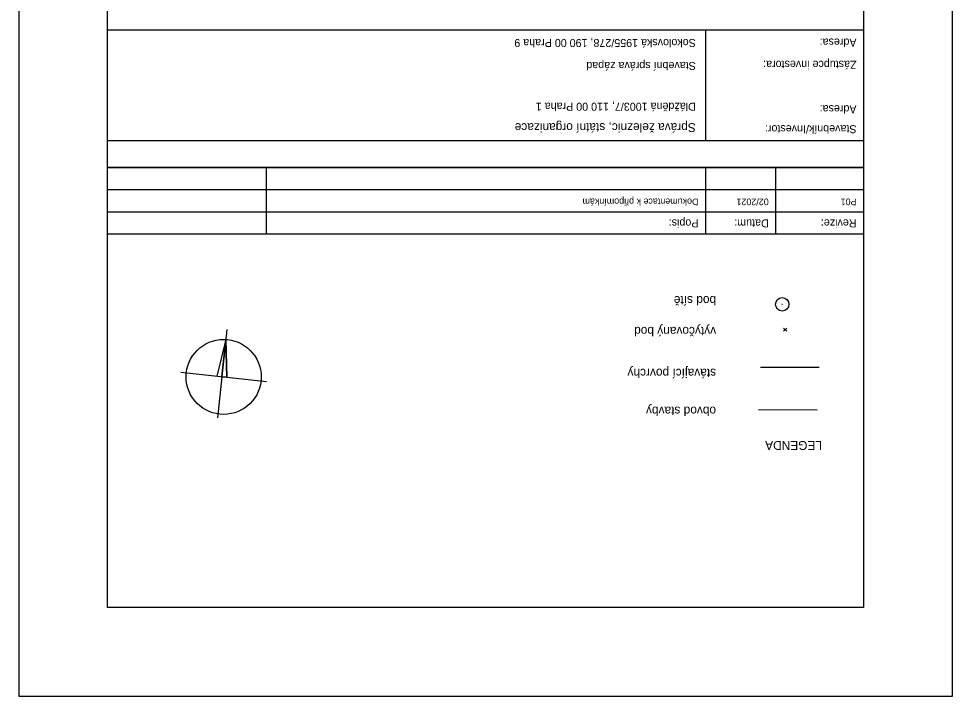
# Model space of a CAD drawing. Extents: x -728476.8 to -728424.3, y -1073086.9 to -1073012.7.
# Drawn here: x -728476.8 to -728424.3, y -1073086.9 to -1073048.8 of the extents above; entities that cross this region are included whole.
import ezdxf

# ---------------------------------------------------------------- set-up
doc = ezdxf.new("R2010")
doc.units = 0
for name, color, linetype in [('_NOR-šraf_+-0', 7, 'Continuous'), ('_NOR-šraf_+12', 7, 'Continuous'), ('A1_OBVOD Spravy železnic', 7, 'Continuous'), ('B3_body_popiska', 7, 'Continuous'), ('Default', 7, 'Continuous'), ('KOS_nové prvky VO', 7, 'Continuous'), ('KTA_členění PS a SO', 7, 'Continuous'), ('ZA_02_Dočasný_do_1_roku', 7, 'Continuous'), ('ZZZ_popisky', 7, 'Continuous')]:
    doc.layers.add(name, color=color, linetype=linetype)

# ---------------------------------------------------------------- blocks, each defined once
blk = doc.blocks.new('C692')
at = {"layer": 'ZA_02_Dočasný_do_1_roku'}
for p, q in [((-0.018, 0.018), (0.018, -0.018)), ((-0.018, -0.018), (0.018, 0.018))]:
    blk.add_line(p, q, dxfattribs=at)
blk = doc.blocks.new('C015')
at = {"layer": 'B3_body_popiska'}
blk.add_line((-0.005, 0), (0.005, 0), dxfattribs=at)
blk.add_circle((0, 0), 0.0756, dxfattribs=at)

msp = doc.modelspace()

# ---------------------------------------------------------------- linework, layer by layer
at = {"layer": '_NOR-šraf_+-0'}
msp.add_line((-728438.176, -1073049.404), (-728438.176, -1073055.654), dxfattribs=at)
msp.add_lwpolyline([(-728429.288, -1073055.654), (-728471.788, -1073055.654), (-728471.788, -1073049.404), (-728429.288, -1073049.404)], close=True, dxfattribs=at)
at = {"layer": '_NOR-šraf_+12'}
for p, q in [((-728431.771, -1073068.408), (-728435.078, -1073068.405)), ((-728431.883, -1073070.797), (-728435.19, -1073070.793))]:
    msp.add_line(p, q, dxfattribs=at)
at = {"layer": 'Default'}
msp.add_lwpolyline([(-728424.288, -1073012.654), (-728476.788, -1073012.654), (-728476.788, -1073086.904), (-728424.288, -1073086.904)], close=True, dxfattribs=at)
msp.add_lwpolyline([(-728424.288, -1073012.654), (-728476.788, -1073012.654), (-728476.788, -1073086.904), (-728424.288, -1073086.904)], close=True, dxfattribs=at)
at = {"layer": 'KOS_nové prvky VO'}
for p, q in [((-728429.288, -1073057.159), (-728471.788, -1073057.159)), ((-728462.863, -1073057.159), (-728462.863, -1073060.909)), ((-728438.176, -1073057.159), (-728438.176, -1073060.909)), ((-728434.226, -1073057.159), (-728434.226, -1073060.909)), ((-728429.288, -1073058.409), (-728471.788, -1073058.409)), ((-728429.288, -1073059.659), (-728471.788, -1073059.659))]:
    msp.add_line(p, q, dxfattribs=at)
msp.add_lwpolyline([(-728429.288, -1073060.909), (-728471.788, -1073060.909), (-728471.788, -1073057.159), (-728429.288, -1073057.159)], close=True, dxfattribs=at)
at = {"layer": 'KTA_členění PS a SO'}
for p, q in [((-728465.081, -1073066.27), (-728465.612, -1073071.243)), ((-728467.679, -1073068.667), (-728462.845, -1073069.199))]:
    msp.add_line(p, q, dxfattribs=at)
msp.add_lwpolyline([(-728465.086, -1073068.947), (-728465.14, -1073066.821), (-728465.642, -1073068.889)], dxfattribs=at)
for points in [[(-728465.364, -1073068.921), (-728465.085, -1073068.952), (-728465.14, -1073066.821)], [(-728465.085, -1073068.952), (-728465.364, -1073068.921), (-728465.14, -1073066.821)]]:
    msp.add_lwpolyline(points, close=True, dxfattribs=at)
msp.add_circle((-728465.262, -1073068.933), 2.111, dxfattribs=at)
at = {"layer": 'ZZZ_popisky'}
msp.add_lwpolyline([(-728429.288, -1073081.904), (-728471.788, -1073081.904), (-728471.788, -1073016.904), (-728429.288, -1073016.904)], close=True, dxfattribs=at)

# ---------------------------------------------------------------- block references
at = {"layer": '_NOR-šraf_+12', "xscale": 5, "yscale": 5}
for name, p in [('C015', (-728433.854, -1073064.85)), ('C692', (-728433.689, -1073066.274))]:
    msp.add_blockref(name, p, dxfattribs=at)

# ---------------------------------------------------------------- texts
at = {"layer": '_NOR-šraf_+-0'}
for s, height, p in [('Adresa:', 0.45, (-728429.675, -1073049.898)), ('Zástupce investora:', 0.45, (-728429.675, -1073051.148)), ('Adresa:', 0.45, (-728429.675, -1073053.648)), ('Správa železnic, státní organizace', 0.5, (-728438.713, -1073054.66)), ('Stavebník/Investor:', 0.45, (-728429.675, -1073054.773))]:
    msp.add_text(s, height=height, rotation=180, dxfattribs=at).set_placement(p)
at = {"layer": '_NOR-šraf_+12'}
for s, p in [('bod sítě', (-728437.57, -1073064.387)), ('vytyčovaný bod', (-728437.572, -1073066.12)), ('stávající povrchy', (-728437.574, -1073068.474)), ('obvod stavby', (-728437.574, -1073070.606)), ('LEGENDA', (-728431.618, -1073072.541))]:
    msp.add_text(s, height=0.5, rotation=180, dxfattribs=at).set_placement(p)
at = {"layer": 'A1_OBVOD Spravy železnic'}
for s, p in [('Sokolovská 1955/278, 190 00 Praha 9', (-728438.713, -1073049.925)), ('Stavební správa západ', (-728438.713, -1073051.214)), ('Dlážděná 1003/7, 110 00 Praha 1', (-728438.713, -1073053.509))]:
    msp.add_text(s, height=0.45, rotation=180, dxfattribs=at).set_placement(p)
at = {"layer": 'KOS_nové prvky VO'}
for s, height, p in [('Dokumentace k připomínkám', 0.375, (-728438.563, -1073058.897)), ('02/2021', 0.375, (-728434.613, -1073058.897)), ('P01', 0.375, (-728429.675, -1073058.897)), ('Popis:', 0.45, (-728438.563, -1073060.072)), ('Datum:', 0.45, (-728434.613, -1073060.072)), ('Revize:', 0.45, (-728429.675, -1073060.072))]:
    msp.add_text(s, height=height, rotation=180, dxfattribs=at).set_placement(p)

doc.saveas('drawing.dxf')
